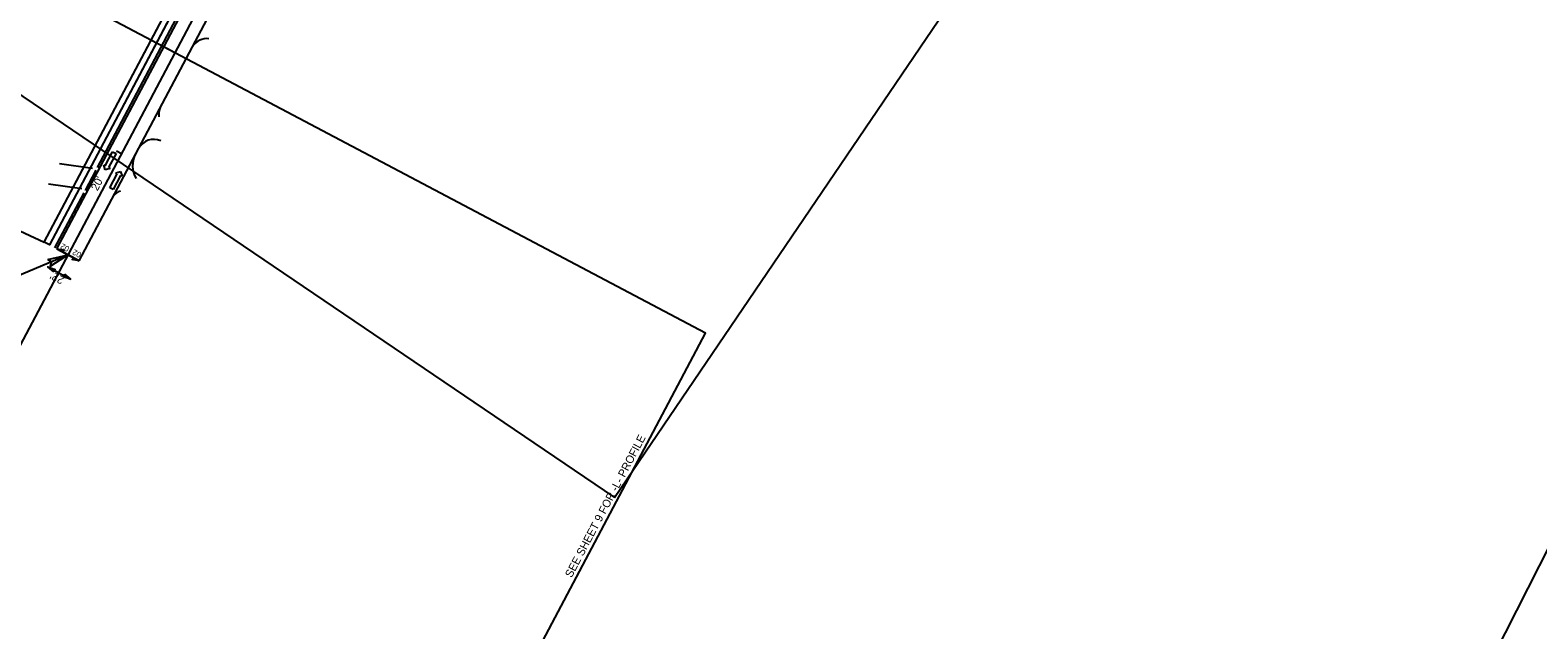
# Model space of a CAD drawing. Extents: x 1974386 to 1979988, y 776712 to 784860.
# Drawn here: x 1975893 to 1977212, y 778330 to 778855 of the extents above; entities that cross this region are included whole.
import ezdxf

# ---------------------------------------------------------------- set-up
doc = ezdxf.new("R2010")
doc.units = 0
for name, color, linetype in [('Default', 7, 'Continuous'), ('Old_Level_11', 7, 'Continuous'), ('Prop Conc 2ft 6in Curb and Gutter', 7, 'Continuous'), ('Prop Conc 4in Sidewalk', 7, 'Continuous'), ('Prop Conc Drive Drop Type', 7, 'Continuous'), ('Prop Dimension', 7, 'Continuous'), ('Prop Dimension Text', 7, 'Continuous'), ('Prop DSN Text', 7, 'Continuous'), ('Prop EOT', 7, 'Continuous'), ('Prop Horizontal Alignment', 7, 'Continuous'), ('Prop Horizontal Alignment Station Label', 7, 'Continuous'), ('Prop Horizontal Alignment Tick Large', 7, 'Continuous'), ('Prop Horizontal Alignment Tick Small', 7, 'Continuous'), ('Prop Lane Arrow CELL', 7, 'Continuous'), ('Prop Superelevation  Arrow CELL', 7, 'Continuous'), ('Prop Superelevation Label', 7, 'Continuous'), ('Prop Terminator CELL', 7, 'Continuous'), ('Sheet Layout Plan Border', 7, 'Continuous')]:
    doc.layers.add(name, color=color, linetype=linetype)

msp = doc.modelspace()

# ---------------------------------------------------------------- linework, layer by layer
at = {"layer": 'Default'}
msp.add_lwpolyline([(1978010, 784859.9), (1974385.9, 777715.1), (1976364, 776711.7), (1979988.1, 783856.5)], close=True, dxfattribs=at)
at = {"layer": 'Old_Level_11'}
msp.add_line((1975925.9, 778658.1), (1975316.6, 778402), dxfattribs=at)
msp.add_lwpolyline([(1975908.1, 778654), (1975925.9, 778658.1), (1975910.5, 778648.2), (1975911.4, 778652)], close=True, dxfattribs=at)
at = {"layer": 'Prop Conc 2ft 6in Curb and Gutter'}
for p, q in [((1975951.6, 778734.5), (1976046.2, 778913.5)), ((1975914.4, 778664.2), (1975939.9, 778712.4))]:
    msp.add_line(p, q, dxfattribs=at)
at = {"layer": 'Prop Conc 4in Sidewalk'}
for p, q in [((1975905.1, 778669.1), (1976036.9, 778918.4)), ((1976041.2, 778915.8), (1975909.6, 778666.8)), ((1975909.6, 778666.8), (1975905.1, 778669.1))]:
    msp.add_line(p, q, dxfattribs=at)
msp.add_lwpolyline([(1976168.5, 779187.7), (1976173, 779185.4), (1976041.2, 778915.8), (1975909.6, 778666.8), (1975905.1, 778669.1), (1976036.9, 778918.4)], close=True, dxfattribs=at)
at = {"layer": 'Prop Conc Drive Drop Type'}
msp.add_line((1975941.1, 778714.6), (1975950.4, 778732.3), dxfattribs=at)
at = {"layer": 'Prop Dimension'}
msp.add_line((1975908.1, 778647.5), (1975928.1, 778636.9), dxfattribs=at)
at = {"layer": 'Prop DSN Text'}
msp.add_line((1975828.7, 778704.6), (1975905.1, 778669.1), dxfattribs=at)
at = {"layer": 'Prop EOT'}
for p, q in [((1975935.6, 778653), (1976126.4, 779013.8)), ((1975916.2, 778663.3), (1976048, 778912.5)), ((1975918.5, 778738), (1975947.3, 778733.9)), ((1975908.8, 778720.3), (1975938, 778716.2)), ((1975916.2, 778663.3), (1975935.6, 778653))]:
    msp.add_line(p, q, dxfattribs=at)
for centre, radius, start, end in [((1976047.4, 778832.4), 15, 83.3224, 147.0348), ((1976019.3, 778781.1), 14.1, 154.3016, 188.5393), ((1976000.9, 778744.2), 15, 66.0165, 152.1381), ((1976003.4, 778736.1), 21.1, 150.9461, 211.7062), ((1975973.7, 778704.5), 9.58, 102.2032, 150.1859)]:
    msp.add_arc(centre, radius, start, end, dxfattribs=at)
at = {"layer": 'Prop Horizontal Alignment'}
msp.add_line((1975785.7, 778392.9), (1976247.2, 779265.9), dxfattribs=at)
at = {"layer": 'Prop Horizontal Alignment Tick Large'}
msp.add_line((1976019.4, 778834.9), (1976012.3, 778838.7), dxfattribs=at)
at = {"layer": 'Prop Horizontal Alignment Tick Small'}
for p, q in [((1975972.6, 778746.5), (1975968.2, 778748.9)), ((1975925.9, 778658.1), (1975921.5, 778660.5))]:
    msp.add_line(p, q, dxfattribs=at)
at = {"layer": 'Prop Lane Arrow CELL'}
for p, q in [((1975958.4, 778736), (1975964.9, 778748.4)), ((1975967.9, 778746.9), (1975961.3, 778734.5)), ((1975964.9, 778748.4), (1975967.9, 778746.9)), ((1975958.4, 778732.5), (1975957.1, 778736.8)), ((1975957.1, 778736.8), (1975958.4, 778736)), ((1975962.6, 778733.8), (1975958.4, 778732.5)), ((1975961.3, 778734.5), (1975962.6, 778733.8)), ((1975962.4, 778716.8), (1975968.9, 778729.1)), ((1975971.8, 778727.6), (1975965.3, 778715.2)), ((1975967.6, 778729.8), (1975971.8, 778731.2)), ((1975968.9, 778729.1), (1975967.6, 778729.8)), ((1975971.8, 778731.2), (1975973.2, 778726.9)), ((1975973.2, 778726.9), (1975971.8, 778727.6)), ((1975965.3, 778715.2), (1975962.4, 778716.8))]:
    msp.add_line(p, q, dxfattribs=at)
at = {"layer": 'Prop Superelevation  Arrow CELL'}
for p in [(1975916.2, 778663.3), (1975935.6, 778653)]:
    msp.add_line(p, (1975925.9, 778658.1), dxfattribs=at)
for points in [[(1975916.2, 778663.3), (1975922.4, 778662.2), (1975920.3, 778661.1)], [(1975935.6, 778653), (1975929.4, 778654), (1975931.6, 778655.1)]]:
    msp.add_lwpolyline(points, close=True, dxfattribs=at)
at = {"layer": 'Prop Terminator CELL'}
for points in [[(1975913.5, 778643.4), (1975908.1, 778647.5), (1975914.6, 778645.4), (1975913.3, 778644.8)], [(1975922.7, 778641.1), (1975928.1, 778636.9), (1975921.6, 778639), (1975922.9, 778639.7)]]:
    msp.add_lwpolyline(points, close=True, dxfattribs=at)
at = {"layer": 'Sheet Layout Plan Border'}
for points in [[(1976403.9, 778445.7), (1977189.9, 779604.2), (1976321, 780193.7), (1975535, 779035.2)], [(1974902.4, 777845.2), (1975830.6, 777354.5), (1975830.6, 777354.5), (1976483.5, 778589.6), (1976483.5, 778589.6), (1975555.2, 779080.3), (1975555.2, 779080.3)]]:
    msp.add_lwpolyline(points, close=True, dxfattribs=at)

# ---------------------------------------------------------------- texts
at = {"layer": 'Prop Dimension Text'}
for s, rotation, p in [("20'", 62.1381, (1975951.6, 778713.6)), ("22'", 152.2175, (1975923.3, 778638.1))]:
    msp.add_text(s, height=7, rotation=rotation, dxfattribs=at).set_placement(p)
at = {"layer": 'Prop Horizontal Alignment Station Label'}
msp.add_text('SEE SHEET 9 FOR -L- PROFILE', height=7, rotation=62.1754, dxfattribs=at).set_placement((1976366.4, 778375))
at = {"layer": 'Prop Superelevation Label'}
for p in [(1975927.5, 778664.9), (1975938, 778659.7)]:
    msp.add_text('02', height=5, rotation=152.1381, dxfattribs=at).set_placement(p)

doc.saveas('drawing.dxf')
